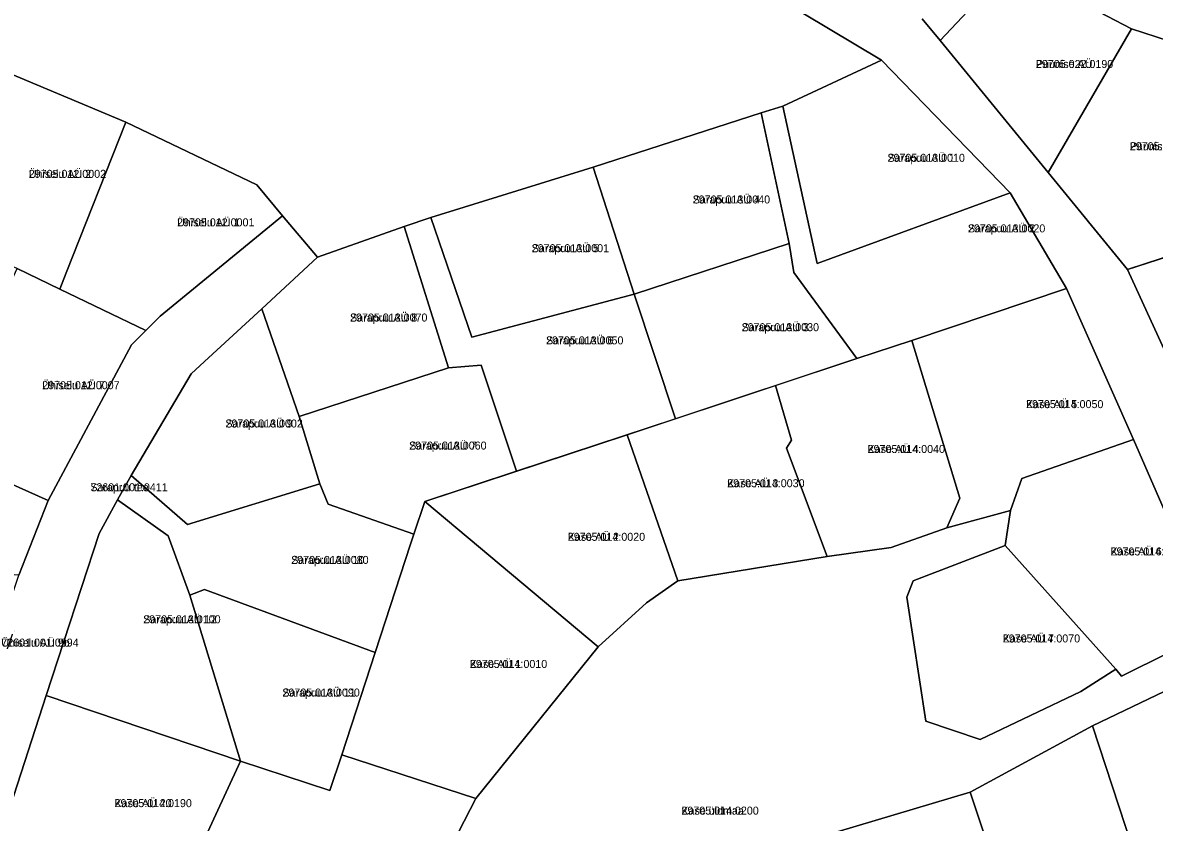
# Model space of a CAD drawing. Extents: x 504287 to 537970, y 6539941 to 6586214.
# Drawn here: x 519273.8 to 519486, y 6563285.9 to 6563435.8 of the extents above; entities that cross this region are included whole.
import ezdxf

# ---------------------------------------------------------------- set-up
doc = ezdxf.new("R2010")
doc.units = 0
for name, color, linetype in [('L_AADRESS', 7, 'Continuous'), ('PIIR', 7, 'Continuous'), ('TUNNUS', 7, 'Continuous')]:
    doc.layers.add(name, color=color, linetype=linetype)

msp = doc.modelspace()

# ---------------------------------------------------------------- linework, layer by layer
at = {"layer": 'PIIR'}
for points in [[(519350.47, 6563485.2), (519381, 6563460.99), (519434.83, 6563428.79), (519416.35, 6563420.15), (519412.28, 6563418.89), (519380.79, 6563408.69), (519350.37, 6563399.28), (519345.34, 6563397.59), (519329.1, 6563391.84), (519322.55, 6563399.61), (519317.71, 6563405.41), (519293.21, 6563417.16), (519269.41, 6563427.1), (519243.82, 6563438.48), (519226.15, 6563445.74), (519326.38, 6563519.01)], [(519456.13, 6563443.47), (519463.45, 6563444.21), (519481.71, 6563434.65), (519466.1, 6563407.74), (519445.87, 6563432.43)], [(519466.1, 6563407.74), (519481.71, 6563434.65), (519495.6, 6563430.16), (519496.67, 6563394.64), (519480.94, 6563389.54)], [(519434.83, 6563428.79), (519458.98, 6563403.9), (519422.79, 6563390.65), (519416.35, 6563420.15)], [(519269.41, 6563427.1), (519293.21, 6563417.16), (519281.99, 6563388.88), (519280.8, 6563385.86), (519272.83, 6563389.69), (519256.76, 6563396.34), (519258.11, 6563399.62)], [(519380.78, 6563408.74), (519412.28, 6563418.89), (519417.56, 6563394.38), (519388.49, 6563384.93)], [(519430.23, 6563372.83), (519418.43, 6563388.98), (519417.56, 6563394.38), (519412.28, 6563418.89), (519416.35, 6563420.15), (519422.79, 6563390.65), (519458.98, 6563403.9), (519469.54, 6563386), (519440.52, 6563376.25)], [(519293.21, 6563417.16), (519317.71, 6563405.41), (519322.55, 6563399.61), (519299.61, 6563380.78), (519296.93, 6563378.08), (519280.8, 6563385.86), (519281.99, 6563388.88)], [(519380.79, 6563408.69), (519388.49, 6563384.93), (519358.04, 6563376.86), (519350.37, 6563399.28)], [(519243.96, 6563248.8), (519257.06, 6563280.53), (519262.44, 6563297.56), (519267.48, 6563315.28), (519269.57, 6563314.59), (519272.18, 6563321.86), (519269.95, 6563322.75), (519273.12, 6563332.24), (519278.63, 6563346.24), (519294.26, 6563375.39), (519296.93, 6563378.08), (519299.61, 6563380.78), (519322.55, 6563399.61), (519329.1, 6563391.84), (519318.65, 6563382.18), (519307.91, 6563372.29), (519305.41, 6563369.96), (519294.2, 6563350.93), (519291.63, 6563346.35), (519288.21, 6563340.08), (519278.22, 6563309.66), (519267.39, 6563276.29), (519254.76, 6563238.59)], [(519359.79, 6563371.63), (519353.69, 6563371.1), (519345.34, 6563397.59), (519350.37, 6563399.28), (519358.04, 6563376.86), (519388.49, 6563384.93), (519396.23, 6563361.56), (519366.43, 6563351.72)], [(519318.65, 6563382.18), (519329.1, 6563391.84), (519345.34, 6563397.59), (519353.69, 6563371.1), (519325.66, 6563361.96)], [(519480.94, 6563389.54), (519501.52, 6563396.17), (519515.6, 6563359.49), (519497.41, 6563353.65)], [(519417.56, 6563394.38), (519418.43, 6563388.98), (519430.23, 6563372.83), (519396.23, 6563361.56), (519388.49, 6563384.93)], [(519272.83, 6563389.69), (519280.8, 6563385.86), (519296.93, 6563378.08), (519294.26, 6563375.39), (519278.63, 6563346.24), (519258.09, 6563355.42), (519271.59, 6563386.95)], [(519447.1, 6563341.1), (519449.51, 6563346.7), (519440.52, 6563376.25), (519469.54, 6563386), (519482.11, 6563357.67), (519461.15, 6563350.34), (519459.01, 6563344.37)], [(519318.65, 6563382.18), (519325.66, 6563361.96), (519329.52, 6563349.33), (519304.74, 6563341.74), (519294.2, 6563350.93), (519305.41, 6563369.96), (519307.91, 6563372.29)], [(519417.03, 6563356.07), (519417.98, 6563357.54), (519414.98, 6563367.78), (519430.23, 6563372.83), (519440.52, 6563376.25), (519449.51, 6563346.7), (519447.1, 6563341.1), (519436.68, 6563337.4), (519424.69, 6563335.73)], [(519329.52, 6563349.33), (519325.66, 6563361.96), (519353.69, 6563371.1), (519359.79, 6563371.63), (519366.43, 6563351.72), (519349.23, 6563346.05), (519347.2, 6563339.93), (519331.09, 6563345.54)], [(519387.16, 6563358.55), (519414.98, 6563367.78), (519417.98, 6563357.54), (519417.03, 6563356.07), (519424.69, 6563335.73), (519396.65, 6563331.16)], [(519238.62, 6563363.64), (519241.56, 6563363.61), (519251.76, 6563357.61), (519258.09, 6563355.42), (519278.63, 6563346.24), (519273.12, 6563332.24), (519270.45, 6563332.44), (519243.61, 6563344.49), (519239.78, 6563346.21), (519240.44, 6563349.13)], [(519387.16, 6563358.55), (519396.65, 6563331.16), (519390.78, 6563327.07), (519381.7, 6563318.8), (519349.23, 6563346.05)], [(519479.81, 6563313.29), (519478.75, 6563314.65), (519458.01, 6563337.81), (519459.01, 6563344.37), (519461.15, 6563350.34), (519482.11, 6563357.67), (519497.57, 6563322.12)], [(519331.09, 6563345.54), (519347.2, 6563339.93), (519346.56, 6563338.03), (519339.94, 6563317.77), (519307.96, 6563329.54), (519305.15, 6563328.51), (519301.11, 6563339.64), (519291.63, 6563346.35), (519294.2, 6563350.93), (519304.74, 6563341.74), (519329.52, 6563349.33)], [(519288.21, 6563340.08), (519291.63, 6563346.35), (519301.11, 6563339.64), (519305.15, 6563328.51), (519314.69, 6563297.36), (519278.22, 6563309.66)], [(519339.94, 6563317.77), (519346.56, 6563338.03), (519347.2, 6563339.93), (519349.23, 6563346.05), (519381.7, 6563318.8), (519358.81, 6563290.37), (519333.66, 6563298.58)], [(519439.57, 6563328.09), (519440.77, 6563331.16), (519458.01, 6563337.81), (519478.75, 6563314.65), (519472.21, 6563310.42), (519453.36, 6563301.45), (519443.13, 6563304.86)], [(519305.15, 6563328.51), (519307.96, 6563329.54), (519339.94, 6563317.77), (519333.66, 6563298.58), (519331.41, 6563291.91), (519314.69, 6563297.36)], [(519474.38, 6563303.98), (519499.82, 6563316.19), (519511.52, 6563279.21), (519485.51, 6563270.1)], [(519314.69, 6563297.36), (519307.34, 6563281.57), (519292.55, 6563267.85), (519267.39, 6563276.29), (519278.22, 6563309.66)], [(519451.48, 6563291.56), (519474.38, 6563303.98), (519485.51, 6563270.1), (519461.25, 6563262.14)], [(519314.69, 6563297.36), (519331.41, 6563291.91), (519333.66, 6563298.58), (519358.81, 6563290.37), (519350.08, 6563273.49), (519346.23, 6563268.99), (519341.87, 6563265), (519331.44, 6563257.39), (519307.34, 6563281.57)], [(519426.55, 6563284.12), (519451.48, 6563291.56), (519461.25, 6563262.14), (519436.64, 6563254.15)]]:
    msp.add_lwpolyline(points, close=True, dxfattribs=at)
for points in [[(519591.71, 6563035.32), (519588.48, 6563045.08), (519571.99, 6563095.18), (519563.24, 6563121.78), (519555.53, 6563145.56), (519553.5, 6563151.6), (519541.01, 6563189.63), (519527.97, 6563230.8), (519524.82, 6563240.31), (519511.52, 6563279.21), (519499.82, 6563316.19), (519497.57, 6563322.12), (519482.11, 6563357.67), (519469.54, 6563386), (519458.98, 6563403.9), (519434.83, 6563428.79), (519381, 6563460.99)], [(519595.41, 6563435.99), (519571.74, 6563432.58), (519545.04, 6563430.03), (519517.03, 6563429.4), (519495.6, 6563430.16), (519481.71, 6563434.65), (519463.45, 6563444.21)], [(519456.13, 6563443.47), (519445.87, 6563432.43), (519442.49, 6563436.49)], [(519442.49, 6563436.49), (519445.87, 6563432.43), (519466.1, 6563407.74), (519480.94, 6563389.54), (519497.41, 6563353.65), (519499.23, 6563349.42), (519507.87, 6563330.09), (519515.92, 6563304.72), (519523.48, 6563281.51), (519531.57, 6563258.56), (519538.85, 6563236.49), (519540.44, 6563231.06), (519552.79, 6563193.12), (519562.73, 6563161.59), (519564.41, 6563155.98), (519578.72, 6563112.4), (519590.45, 6563075.98), (519591.52, 6563072.05), (519599.74, 6563045.34), (519653.53, 6562903.18)], [(519350.08, 6563273.49), (519358.81, 6563290.37), (519381.7, 6563318.8), (519390.78, 6563327.07), (519396.65, 6563331.16), (519424.69, 6563335.73), (519436.68, 6563337.4), (519447.1, 6563341.1), (519459.01, 6563344.37), (519458.01, 6563337.81), (519440.77, 6563331.16), (519439.57, 6563328.09), (519443.13, 6563304.86), (519453.36, 6563301.45), (519472.21, 6563310.42), (519478.75, 6563314.65), (519479.81, 6563313.29), (519497.57, 6563322.12)], [(519499.82, 6563316.19), (519474.38, 6563303.98), (519451.48, 6563291.56), (519426.55, 6563284.12), (519400.49, 6563279.08), (519375.08, 6563275.85), (519366.92, 6563273.4), (519362.95, 6563271.76), (519345.22, 6563257.69), (519320.37, 6563242.86), (519293.15, 6563234.92), (519254.72, 6563230.35)]]:
    msp.add_lwpolyline(points, dxfattribs=at)

# ---------------------------------------------------------------- texts
at = {"layer": 'L_AADRESS'}
for s, p in [('Püünise AÜ 19', (519463.79, 6563427.3)), ('Püünise AÜ 18', (519481.39, 6563411.89)), ('Sarapuu AÜ 1', (519435.98, 6563409.72)), ('Ühiselu AÜ 2', (519274.98, 6563406.71)), ('Sarapuu AÜ 4', (519399.46, 6563401.91)), ('Ühiselu AÜ 1', (519302.79, 6563397.62)), ('Sarapuu AÜ 2', (519451.05, 6563396.49)), ('Sarapuu AÜ 5', (519369.27, 6563392.78)), ('Sarapuu AÜ 8', (519335.22, 6563379.78)), ('Sarapuu AÜ 3', (519408.63, 6563377.97)), ('Sarapuu AÜ 6', (519371.96, 6563375.5)), ('Ühiselu AÜ 7', (519277.51, 6563367.09)), ('Kase AÜ 5', (519461.94, 6563363.55)), ('Sarapuu AÜ 9', (519311.86, 6563359.92)), ('Sarapuu AÜ 7', (519346.31, 6563355.78)), ('Kase AÜ 4', (519432.24, 6563355.14)), ('Kase AÜ 3', (519405.92, 6563348.72)), ('Sarapuu tee', (519286.53, 6563347.97)), ('Kase AÜ 2', (519376.03, 6563338.68)), ('Kase AÜ 6', (519477.79, 6563335.94)), ('Sarapuu AÜ 10', (519324.19, 6563334.35)), ('Sarapuu AÜ 12', (519296.45, 6563323.22)), ('Ühiselu AÜ 9b', (519269.83, 6563318.85)), ('Kase AÜ 7', (519457.58, 6563319.63)), ('Kase AÜ 1', (519357.68, 6563314.85)), ('Sarapuu AÜ 11', (519322.54, 6563309.49)), ('Kase AÜ 20', (519291.06, 6563288.76)), ('Kase üldmaa', (519397.33, 6563287.36))]:
    msp.add_text(s, height=1.5, dxfattribs=at).set_placement(p)
at = {"layer": 'TUNNUS'}
for s, p in [('29705:022:0190', (519463.79, 6563427.3)), ('29705:022:0180', (519481.39, 6563411.89)), ('29705:013:0010', (519435.98, 6563409.72)), ('29705:012:0002', (519274.98, 6563406.71)), ('29705:013:0040', (519399.46, 6563401.91)), ('29705:012:0001', (519302.79, 6563397.62)), ('29705:013:0020', (519451.05, 6563396.49)), ('29705:013:0001', (519369.27, 6563392.78)), ('29705:013:0070', (519335.22, 6563379.78)), ('29705:013:0030', (519408.63, 6563377.97)), ('29705:013:0050', (519371.96, 6563375.5)), ('29705:012:0007', (519277.51, 6563367.09)), ('29705:014:0050', (519461.94, 6563363.55)), ('29705:013:0002', (519311.86, 6563359.92)), ('29705:013:0060', (519346.31, 6563355.78)), ('29705:014:0040', (519432.24, 6563355.14)), ('72601:001:0411', (519286.53, 6563347.97)), ('29705:014:0030', (519405.92, 6563348.72)), ('29705:014:0020', (519376.03, 6563338.68)), ('29705:013:0080', (519324.19, 6563334.35)), ('29705:014:0060', (519477.79, 6563335.94)), ('29705:013:0100', (519296.45, 6563323.22)), ('29705:014:0070', (519457.58, 6563319.63)), ('72601:001:0994', (519269.83, 6563318.85)), ('29705:014:0010', (519357.68, 6563314.85)), ('29705:013:0090', (519322.54, 6563309.49)), ('29705:014:0190', (519291.06, 6563288.76)), ('29705:014:0200', (519397.33, 6563287.36))]:
    msp.add_text(s, height=1.5, dxfattribs=at).set_placement(p)

doc.saveas('drawing.dxf')
